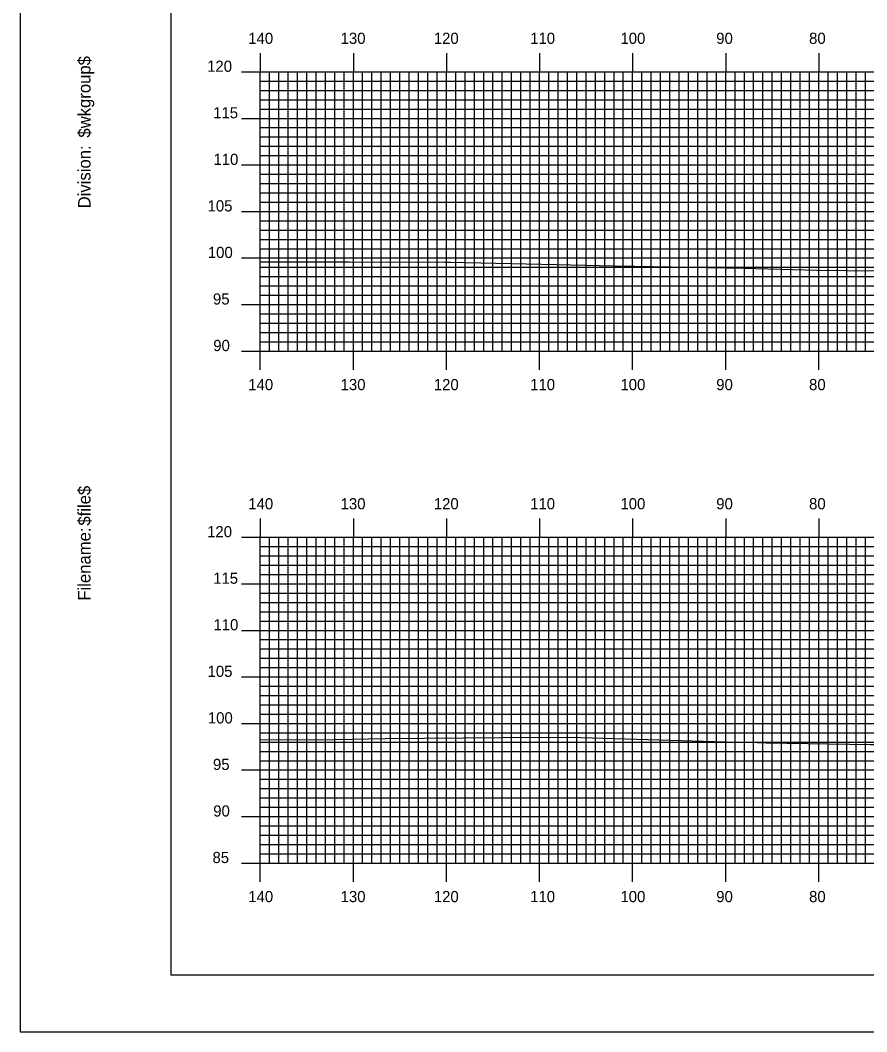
# Model space of a CAD drawing. Extents: x 1787369 to 1787713, y 442591 to 442811.
# Drawn here: x 1787369.3 to 1787460.2, y 442590.5 to 442699.2 of the extents above; entities that cross this region are included whole.
import ezdxf

# ---------------------------------------------------------------- set-up
doc = ezdxf.new("R2010")
doc.units = 0
for name, color, linetype in [('BORDER', 7, 'Continuous'), ('H_V ANNOTATION', 7, 'Continuous'), ('MAJOR', 7, 'Continuous'), ('MINOR', 7, 'Continuous'), ('PLOT BOUNDARY', 7, 'Continuous'), ('S_Roadway_Centerline', 7, 'Continuous')]:
    doc.layers.add(name, color=color, linetype=linetype)

msp = doc.modelspace()

# ---------------------------------------------------------------- linework, layer by layer
at = {"layer": 'BORDER'}
msp.add_lwpolyline([(1787385.5, 442596.67), (1787705.5, 442596.67), (1787705.5, 442806.67), (1787385.5, 442806.67)], close=True, dxfattribs=at)
at = {"layer": 'MAJOR'}
for p, q in [((1787395.1, 442695.67), (1787395.1, 442693.67)), ((1787405.1, 442695.67), (1787405.1, 442693.67)), ((1787415.1, 442695.67), (1787415.1, 442693.67)), ((1787425.1, 442695.67), (1787425.1, 442693.67)), ((1787435.1, 442695.67), (1787435.1, 442693.67)), ((1787445.1, 442695.67), (1787445.1, 442693.67)), ((1787455.1, 442695.67), (1787455.1, 442693.67)), ((1787393.1, 442693.67), (1787395.1, 442693.67)), ((1787395.1, 442693.67), (1787675.1, 442693.67)), ((1787395.1, 442663.67), (1787395.1, 442693.67)), ((1787395.1, 442663.67), (1787395.1, 442693.67)), ((1787395.1, 442693.67), (1787675.1, 442693.67)), ((1787405.1, 442663.67), (1787405.1, 442693.67)), ((1787415.1, 442663.67), (1787415.1, 442693.67)), ((1787425.1, 442663.67), (1787425.1, 442693.67)), ((1787435.1, 442663.67), (1787435.1, 442693.67)), ((1787445.1, 442663.67), (1787445.1, 442693.67)), ((1787455.1, 442663.67), (1787455.1, 442693.67)), ((1787393.1, 442688.67), (1787395.1, 442688.67)), ((1787395.1, 442688.67), (1787675.1, 442688.67)), ((1787393.1, 442683.67), (1787395.1, 442683.67)), ((1787395.1, 442683.67), (1787675.1, 442683.67)), ((1787393.1, 442678.67), (1787395.1, 442678.67)), ((1787395.1, 442678.67), (1787675.1, 442678.67)), ((1787393.1, 442673.67), (1787395.1, 442673.67)), ((1787395.1, 442673.67), (1787675.1, 442673.67)), ((1787393.1, 442668.67), (1787395.1, 442668.67)), ((1787395.1, 442668.67), (1787675.1, 442668.67)), ((1787393.1, 442663.67), (1787395.1, 442663.67)), ((1787395.1, 442663.67), (1787675.1, 442663.67)), ((1787395.1, 442663.67), (1787675.1, 442663.67)), ((1787395.1, 442661.66), (1787395.1, 442663.67)), ((1787405.1, 442661.66), (1787405.1, 442663.67)), ((1787415.1, 442661.66), (1787415.1, 442663.67)), ((1787425.1, 442661.66), (1787425.1, 442663.67)), ((1787435.1, 442661.66), (1787435.1, 442663.67)), ((1787445.1, 442661.66), (1787445.1, 442663.67)), ((1787455.1, 442661.66), (1787455.1, 442663.67)), ((1787395.1, 442645.67), (1787395.1, 442643.67)), ((1787405.1, 442645.67), (1787405.1, 442643.67)), ((1787415.1, 442645.67), (1787415.1, 442643.67)), ((1787425.1, 442645.67), (1787425.1, 442643.67)), ((1787435.1, 442645.67), (1787435.1, 442643.67)), ((1787445.1, 442645.67), (1787445.1, 442643.67)), ((1787455.1, 442645.67), (1787455.1, 442643.67)), ((1787393.1, 442643.67), (1787395.1, 442643.67)), ((1787395.1, 442643.67), (1787675.1, 442643.67)), ((1787395.1, 442608.67), (1787395.1, 442643.67)), ((1787395.1, 442608.67), (1787395.1, 442643.67)), ((1787395.1, 442643.67), (1787675.1, 442643.67)), ((1787405.1, 442608.67), (1787405.1, 442643.67)), ((1787415.1, 442608.67), (1787415.1, 442643.67)), ((1787425.1, 442608.67), (1787425.1, 442643.67)), ((1787435.1, 442608.67), (1787435.1, 442643.67)), ((1787445.1, 442608.67), (1787445.1, 442643.67)), ((1787455.1, 442608.67), (1787455.1, 442643.67)), ((1787393.1, 442638.67), (1787395.1, 442638.67)), ((1787395.1, 442638.67), (1787675.1, 442638.67)), ((1787393.1, 442633.67), (1787395.1, 442633.67)), ((1787395.1, 442633.67), (1787675.1, 442633.67)), ((1787393.1, 442628.67), (1787395.1, 442628.67)), ((1787395.1, 442628.67), (1787675.1, 442628.67)), ((1787393.1, 442623.67), (1787395.1, 442623.67)), ((1787395.1, 442623.67), (1787675.1, 442623.67)), ((1787393.1, 442618.67), (1787395.1, 442618.67)), ((1787395.1, 442618.67), (1787675.1, 442618.67)), ((1787393.1, 442613.67), (1787395.1, 442613.67)), ((1787395.1, 442613.67), (1787675.1, 442613.67)), ((1787393.1, 442608.67), (1787395.1, 442608.67)), ((1787395.1, 442608.67), (1787675.1, 442608.67)), ((1787395.1, 442608.67), (1787675.1, 442608.67)), ((1787395.1, 442606.66), (1787395.1, 442608.67)), ((1787405.1, 442606.66), (1787405.1, 442608.67)), ((1787415.1, 442606.66), (1787415.1, 442608.67)), ((1787425.1, 442606.66), (1787425.1, 442608.67)), ((1787435.1, 442606.66), (1787435.1, 442608.67)), ((1787445.1, 442606.66), (1787445.1, 442608.67)), ((1787455.1, 442606.66), (1787455.1, 442608.67))]:
    msp.add_line(p, q, dxfattribs=at)
at = {"layer": 'MINOR'}
for p, q in [((1787396.1, 442663.67), (1787396.1, 442693.67)), ((1787397.1, 442663.67), (1787397.1, 442693.67)), ((1787398.1, 442663.67), (1787398.1, 442693.67)), ((1787399.1, 442663.67), (1787399.1, 442693.67)), ((1787400.1, 442663.67), (1787400.1, 442693.67)), ((1787401.1, 442663.67), (1787401.1, 442693.67)), ((1787402.1, 442663.67), (1787402.1, 442693.67)), ((1787403.1, 442663.67), (1787403.1, 442693.67)), ((1787404.1, 442663.67), (1787404.1, 442693.67)), ((1787406.1, 442663.67), (1787406.1, 442693.67)), ((1787407.1, 442663.67), (1787407.1, 442693.67)), ((1787408.1, 442663.67), (1787408.1, 442693.67)), ((1787409.1, 442663.67), (1787409.1, 442693.67)), ((1787410.1, 442663.67), (1787410.1, 442693.67)), ((1787411.1, 442663.67), (1787411.1, 442693.67)), ((1787412.1, 442663.67), (1787412.1, 442693.67)), ((1787413.1, 442663.67), (1787413.1, 442693.67)), ((1787414.1, 442663.67), (1787414.1, 442693.67)), ((1787416.1, 442663.67), (1787416.1, 442693.67)), ((1787417.1, 442663.67), (1787417.1, 442693.67)), ((1787418.1, 442663.67), (1787418.1, 442693.67)), ((1787419.1, 442663.67), (1787419.1, 442693.67)), ((1787420.1, 442663.67), (1787420.1, 442693.67)), ((1787421.1, 442663.67), (1787421.1, 442693.67)), ((1787422.1, 442663.67), (1787422.1, 442693.67)), ((1787423.1, 442663.67), (1787423.1, 442693.67)), ((1787424.1, 442663.67), (1787424.1, 442693.67)), ((1787426.1, 442663.67), (1787426.1, 442693.67)), ((1787427.1, 442663.67), (1787427.1, 442693.67)), ((1787428.1, 442663.67), (1787428.1, 442693.67)), ((1787429.1, 442663.67), (1787429.1, 442693.67)), ((1787430.1, 442663.67), (1787430.1, 442693.67)), ((1787431.1, 442663.67), (1787431.1, 442693.67)), ((1787432.1, 442663.67), (1787432.1, 442693.67)), ((1787433.1, 442663.67), (1787433.1, 442693.67)), ((1787434.1, 442663.67), (1787434.1, 442693.67)), ((1787436.1, 442663.67), (1787436.1, 442693.67)), ((1787437.1, 442663.67), (1787437.1, 442693.67)), ((1787438.1, 442663.67), (1787438.1, 442693.67)), ((1787439.1, 442663.67), (1787439.1, 442693.67)), ((1787440.1, 442663.67), (1787440.1, 442693.67)), ((1787441.1, 442663.67), (1787441.1, 442693.67)), ((1787442.1, 442663.67), (1787442.1, 442693.67)), ((1787443.1, 442663.67), (1787443.1, 442693.67)), ((1787444.1, 442663.67), (1787444.1, 442693.67)), ((1787446.1, 442663.67), (1787446.1, 442693.67)), ((1787447.1, 442663.67), (1787447.1, 442693.67)), ((1787448.1, 442663.67), (1787448.1, 442693.67)), ((1787449.1, 442663.67), (1787449.1, 442693.67)), ((1787450.1, 442663.67), (1787450.1, 442693.67)), ((1787451.1, 442663.67), (1787451.1, 442693.67)), ((1787452.1, 442663.67), (1787452.1, 442693.67)), ((1787453.1, 442663.67), (1787453.1, 442693.67)), ((1787454.1, 442663.67), (1787454.1, 442693.67)), ((1787456.1, 442663.67), (1787456.1, 442693.67)), ((1787457.1, 442663.67), (1787457.1, 442693.67)), ((1787458.1, 442663.67), (1787458.1, 442693.67)), ((1787459.1, 442663.67), (1787459.1, 442693.67)), ((1787460.1, 442663.67), (1787460.1, 442693.67)), ((1787395.1, 442692.67), (1787675.1, 442692.67)), ((1787395.1, 442692.67), (1787397.11, 442692.67)), ((1787395.1, 442691.67), (1787675.1, 442691.67)), ((1787395.1, 442691.67), (1787397.11, 442691.67)), ((1787395.1, 442690.67), (1787675.1, 442690.67)), ((1787395.1, 442690.67), (1787397.11, 442690.67)), ((1787395.1, 442689.67), (1787675.1, 442689.67)), ((1787395.1, 442689.67), (1787397.11, 442689.67)), ((1787395.1, 442687.67), (1787675.1, 442687.67)), ((1787395.1, 442687.67), (1787397.11, 442687.67)), ((1787395.1, 442686.67), (1787675.1, 442686.67)), ((1787395.1, 442686.67), (1787397.11, 442686.67)), ((1787395.1, 442685.67), (1787675.1, 442685.67)), ((1787395.1, 442685.67), (1787397.11, 442685.67)), ((1787395.1, 442684.67), (1787675.1, 442684.67)), ((1787395.1, 442684.67), (1787397.11, 442684.67)), ((1787395.1, 442682.67), (1787675.1, 442682.67)), ((1787395.1, 442682.67), (1787397.11, 442682.67)), ((1787395.1, 442681.67), (1787675.1, 442681.67)), ((1787395.1, 442681.67), (1787397.11, 442681.67)), ((1787395.1, 442680.67), (1787675.1, 442680.67)), ((1787395.1, 442680.67), (1787397.11, 442680.67)), ((1787395.1, 442679.67), (1787675.1, 442679.67)), ((1787395.1, 442679.67), (1787397.11, 442679.67)), ((1787395.1, 442677.67), (1787675.1, 442677.67)), ((1787395.1, 442677.67), (1787397.11, 442677.67)), ((1787395.1, 442676.67), (1787675.1, 442676.67)), ((1787395.1, 442676.67), (1787397.11, 442676.67)), ((1787395.1, 442675.67), (1787675.1, 442675.67)), ((1787395.1, 442675.67), (1787397.11, 442675.67)), ((1787395.1, 442674.67), (1787675.1, 442674.67)), ((1787395.1, 442674.67), (1787397.11, 442674.67)), ((1787395.1, 442672.67), (1787675.1, 442672.67)), ((1787395.1, 442672.67), (1787397.11, 442672.67)), ((1787395.1, 442671.67), (1787675.1, 442671.67)), ((1787395.1, 442671.67), (1787397.11, 442671.67)), ((1787395.1, 442670.67), (1787675.1, 442670.67)), ((1787395.1, 442670.67), (1787397.11, 442670.67)), ((1787395.1, 442669.67), (1787675.1, 442669.67)), ((1787395.1, 442669.67), (1787397.11, 442669.67)), ((1787395.1, 442667.67), (1787675.1, 442667.67)), ((1787395.1, 442667.67), (1787397.11, 442667.67)), ((1787395.1, 442666.67), (1787675.1, 442666.67)), ((1787395.1, 442666.67), (1787397.11, 442666.67)), ((1787395.1, 442665.67), (1787675.1, 442665.67)), ((1787395.1, 442665.67), (1787397.11, 442665.67)), ((1787395.1, 442664.67), (1787675.1, 442664.67)), ((1787395.1, 442664.67), (1787397.11, 442664.67)), ((1787396.1, 442608.67), (1787396.1, 442643.67)), ((1787397.1, 442608.67), (1787397.1, 442643.67)), ((1787398.1, 442608.67), (1787398.1, 442643.67)), ((1787399.1, 442608.67), (1787399.1, 442643.67)), ((1787400.1, 442608.67), (1787400.1, 442643.67)), ((1787401.1, 442608.67), (1787401.1, 442643.67)), ((1787402.1, 442608.67), (1787402.1, 442643.67)), ((1787403.1, 442608.67), (1787403.1, 442643.67)), ((1787404.1, 442608.67), (1787404.1, 442643.67)), ((1787406.1, 442608.67), (1787406.1, 442643.67)), ((1787407.1, 442608.67), (1787407.1, 442643.67)), ((1787408.1, 442608.67), (1787408.1, 442643.67)), ((1787409.1, 442608.67), (1787409.1, 442643.67)), ((1787410.1, 442608.67), (1787410.1, 442643.67)), ((1787411.1, 442608.67), (1787411.1, 442643.67)), ((1787412.1, 442608.67), (1787412.1, 442643.67)), ((1787413.1, 442608.67), (1787413.1, 442643.67)), ((1787414.1, 442608.67), (1787414.1, 442643.67)), ((1787416.1, 442608.67), (1787416.1, 442643.67)), ((1787417.1, 442608.67), (1787417.1, 442643.67)), ((1787418.1, 442608.67), (1787418.1, 442643.67)), ((1787419.1, 442608.67), (1787419.1, 442643.67)), ((1787420.1, 442608.67), (1787420.1, 442643.67)), ((1787421.1, 442608.67), (1787421.1, 442643.67)), ((1787422.1, 442608.67), (1787422.1, 442643.67)), ((1787423.1, 442608.67), (1787423.1, 442643.67)), ((1787424.1, 442608.67), (1787424.1, 442643.67)), ((1787426.1, 442608.67), (1787426.1, 442643.67)), ((1787427.1, 442608.67), (1787427.1, 442643.67)), ((1787428.1, 442608.67), (1787428.1, 442643.67)), ((1787429.1, 442608.67), (1787429.1, 442643.67)), ((1787430.1, 442608.67), (1787430.1, 442643.67)), ((1787431.1, 442608.67), (1787431.1, 442643.67)), ((1787432.1, 442608.67), (1787432.1, 442643.67)), ((1787433.1, 442608.67), (1787433.1, 442643.67)), ((1787434.1, 442608.67), (1787434.1, 442643.67)), ((1787436.1, 442608.67), (1787436.1, 442643.67)), ((1787437.1, 442608.67), (1787437.1, 442643.67)), ((1787438.1, 442608.67), (1787438.1, 442643.67)), ((1787439.1, 442608.67), (1787439.1, 442643.67)), ((1787440.1, 442608.67), (1787440.1, 442643.67)), ((1787441.1, 442608.67), (1787441.1, 442643.67)), ((1787442.1, 442608.67), (1787442.1, 442643.67)), ((1787443.1, 442608.67), (1787443.1, 442643.67)), ((1787444.1, 442608.67), (1787444.1, 442643.67)), ((1787446.1, 442608.67), (1787446.1, 442643.67)), ((1787447.1, 442608.67), (1787447.1, 442643.67)), ((1787448.1, 442608.67), (1787448.1, 442643.67)), ((1787449.1, 442608.67), (1787449.1, 442643.67)), ((1787450.1, 442608.67), (1787450.1, 442643.67)), ((1787451.1, 442608.67), (1787451.1, 442643.67)), ((1787452.1, 442608.67), (1787452.1, 442643.67)), ((1787453.1, 442608.67), (1787453.1, 442643.67)), ((1787454.1, 442608.67), (1787454.1, 442643.67)), ((1787456.1, 442608.67), (1787456.1, 442643.67)), ((1787457.1, 442608.67), (1787457.1, 442643.67)), ((1787458.1, 442608.67), (1787458.1, 442643.67)), ((1787459.1, 442608.67), (1787459.1, 442643.67)), ((1787460.1, 442608.67), (1787460.1, 442643.67)), ((1787395.1, 442642.67), (1787675.1, 442642.67)), ((1787395.1, 442642.67), (1787397.11, 442642.67)), ((1787395.1, 442641.67), (1787675.1, 442641.67)), ((1787395.1, 442641.67), (1787397.11, 442641.67)), ((1787395.1, 442640.67), (1787675.1, 442640.67)), ((1787395.1, 442640.67), (1787397.11, 442640.67)), ((1787395.1, 442639.67), (1787675.1, 442639.67)), ((1787395.1, 442639.67), (1787397.11, 442639.67)), ((1787395.1, 442637.67), (1787675.1, 442637.67)), ((1787395.1, 442637.67), (1787397.11, 442637.67)), ((1787395.1, 442636.67), (1787675.1, 442636.67)), ((1787395.1, 442636.67), (1787397.11, 442636.67)), ((1787395.1, 442635.67), (1787675.1, 442635.67)), ((1787395.1, 442635.67), (1787397.11, 442635.67)), ((1787395.1, 442634.67), (1787675.1, 442634.67)), ((1787395.1, 442634.67), (1787397.11, 442634.67)), ((1787395.1, 442632.67), (1787675.1, 442632.67)), ((1787395.1, 442632.67), (1787397.11, 442632.67)), ((1787395.1, 442631.67), (1787675.1, 442631.67)), ((1787395.1, 442631.67), (1787397.11, 442631.67)), ((1787395.1, 442630.67), (1787675.1, 442630.67)), ((1787395.1, 442630.67), (1787397.11, 442630.67)), ((1787395.1, 442629.67), (1787675.1, 442629.67)), ((1787395.1, 442629.67), (1787397.11, 442629.67)), ((1787395.1, 442627.67), (1787675.1, 442627.67)), ((1787395.1, 442627.67), (1787397.11, 442627.67)), ((1787395.1, 442626.67), (1787675.1, 442626.67)), ((1787395.1, 442626.67), (1787397.11, 442626.67)), ((1787395.1, 442625.67), (1787675.1, 442625.67)), ((1787395.1, 442625.67), (1787397.11, 442625.67)), ((1787395.1, 442624.67), (1787675.1, 442624.67)), ((1787395.1, 442624.67), (1787397.11, 442624.67)), ((1787395.1, 442622.67), (1787675.1, 442622.67)), ((1787395.1, 442622.67), (1787397.11, 442622.67)), ((1787395.1, 442621.67), (1787675.1, 442621.67)), ((1787395.1, 442621.67), (1787397.11, 442621.67)), ((1787395.1, 442620.67), (1787675.1, 442620.67)), ((1787395.1, 442620.67), (1787397.11, 442620.67)), ((1787395.1, 442619.67), (1787675.1, 442619.67)), ((1787395.1, 442619.67), (1787397.11, 442619.67)), ((1787395.1, 442617.67), (1787675.1, 442617.67)), ((1787395.1, 442617.67), (1787397.11, 442617.67)), ((1787395.1, 442616.67), (1787675.1, 442616.67)), ((1787395.1, 442616.67), (1787397.11, 442616.67)), ((1787395.1, 442615.67), (1787675.1, 442615.67)), ((1787395.1, 442615.67), (1787397.11, 442615.67)), ((1787395.1, 442614.67), (1787675.1, 442614.67)), ((1787395.1, 442614.67), (1787397.11, 442614.67)), ((1787395.1, 442612.67), (1787675.1, 442612.67)), ((1787395.1, 442612.67), (1787397.11, 442612.67)), ((1787395.1, 442611.67), (1787675.1, 442611.67)), ((1787395.1, 442611.67), (1787397.11, 442611.67)), ((1787395.1, 442610.67), (1787675.1, 442610.67)), ((1787395.1, 442610.67), (1787397.11, 442610.67)), ((1787395.1, 442609.67), (1787675.1, 442609.67)), ((1787395.1, 442609.67), (1787397.11, 442609.67))]:
    msp.add_line(p, q, dxfattribs=at)
at = {"layer": 'PLOT BOUNDARY'}
msp.add_lwpolyline([(1787369.32, 442590.55), (1787709.32, 442590.55), (1787709.32, 442810.55), (1787369.32, 442810.55)], close=True, dxfattribs=at)
at = {"layer": 'S_Roadway_Centerline'}
for points in [[(1787395.1, 442673.27), (1787396, 442673.27), (1787399.41, 442673.26), (1787404.67, 442673.26), (1787414.9, 442673.23), (1787415.53, 442673.22), (1787426.91, 442672.97), (1787434.6, 442672.8), (1787435.04, 442672.79), (1787435.35, 442672.78), (1787447.05, 442672.56), (1787454.88, 442672.35), (1787464.57, 442672.24)], [(1787395.1, 442621.95), (1787401.36, 442621.92), (1787408.55, 442622.06), (1787421.06, 442622.15), (1787428.35, 442622.19), (1787446.29, 442621.67), (1787448.47, 442621.61), (1787448.84, 442621.61), (1787449.43, 442621.6), (1787460.61, 442621.41), (1787467.98, 442621.41), (1787478.74, 442621.47), (1787487.8, 442621.44), (1787496.07, 442621.17), (1787507.74, 442620.92), (1787508.9, 442620.88), (1787527.38, 442620.54), (1787531.44, 442620.51), (1787537.84, 442620.28), (1787547.42, 442619.99), (1787555.27, 442619.85), (1787566.74, 442619.43)]]:
    msp.add_lwpolyline(points, dxfattribs=at)

# ---------------------------------------------------------------- texts
at = {"layer": 'BORDER'}
for s, p in [('$wkgroup$', (1787376.87, 442686.6)), ('Division:', (1787376.87, 442679)), ('$file$', (1787376.87, 442644.92)), ('Filename:', (1787376.87, 442636.86))]:
    msp.add_text(s, height=1.339, rotation=90, dxfattribs=at).set_placement(p)
at = {"layer": 'H_V ANNOTATION'}
for s, p in [('140', (1787393.81, 442696.67)), ('130', (1787403.73, 442696.67)), ('120', (1787413.74, 442696.67)), ('110', (1787424.09, 442696.67)), ('100', (1787433.79, 442696.67)), ('90', (1787444.08, 442696.67)), ('80', (1787454.05, 442696.67)), ('120', (1787389.39, 442693.67)), ('115', (1787390.04, 442688.67)), ('110', (1787390.07, 442683.67)), ('105', (1787389.44, 442678.67)), ('100', (1787389.47, 442673.67)), ('95', (1787390.02, 442668.67)), ('90', (1787390.05, 442663.67)), ('140', (1787393.81, 442659.47)), ('130', (1787403.73, 442659.47)), ('120', (1787413.74, 442659.47)), ('110', (1787424.09, 442659.47)), ('100', (1787433.79, 442659.47)), ('90', (1787444.08, 442659.47)), ('80', (1787454.05, 442659.47)), ('140', (1787393.81, 442646.67)), ('130', (1787403.73, 442646.67)), ('120', (1787413.74, 442646.67)), ('110', (1787424.09, 442646.67)), ('100', (1787433.79, 442646.67)), ('90', (1787444.08, 442646.67)), ('80', (1787454.05, 442646.67)), ('120', (1787389.39, 442643.67)), ('115', (1787390.04, 442638.67)), ('110', (1787390.07, 442633.67)), ('105', (1787389.44, 442628.67)), ('100', (1787389.47, 442623.67)), ('95', (1787390.02, 442618.67)), ('90', (1787390.05, 442613.67)), ('85', (1787389.97, 442608.67)), ('140', (1787393.81, 442604.47)), ('130', (1787403.73, 442604.47)), ('120', (1787413.74, 442604.47)), ('110', (1787424.09, 442604.47)), ('100', (1787433.79, 442604.47)), ('90', (1787444.08, 442604.47)), ('80', (1787454.05, 442604.47))]:
    msp.add_text(s, height=1.2, dxfattribs=at).set_placement(p)
at = {"layer": 'MAJOR'}
for p in [(1787395.1, 442663.67), (1787395.1, 442608.67)]:
    msp.add_text('-', height=0.012, dxfattribs=at).set_placement(p)

doc.saveas('drawing.dxf')
